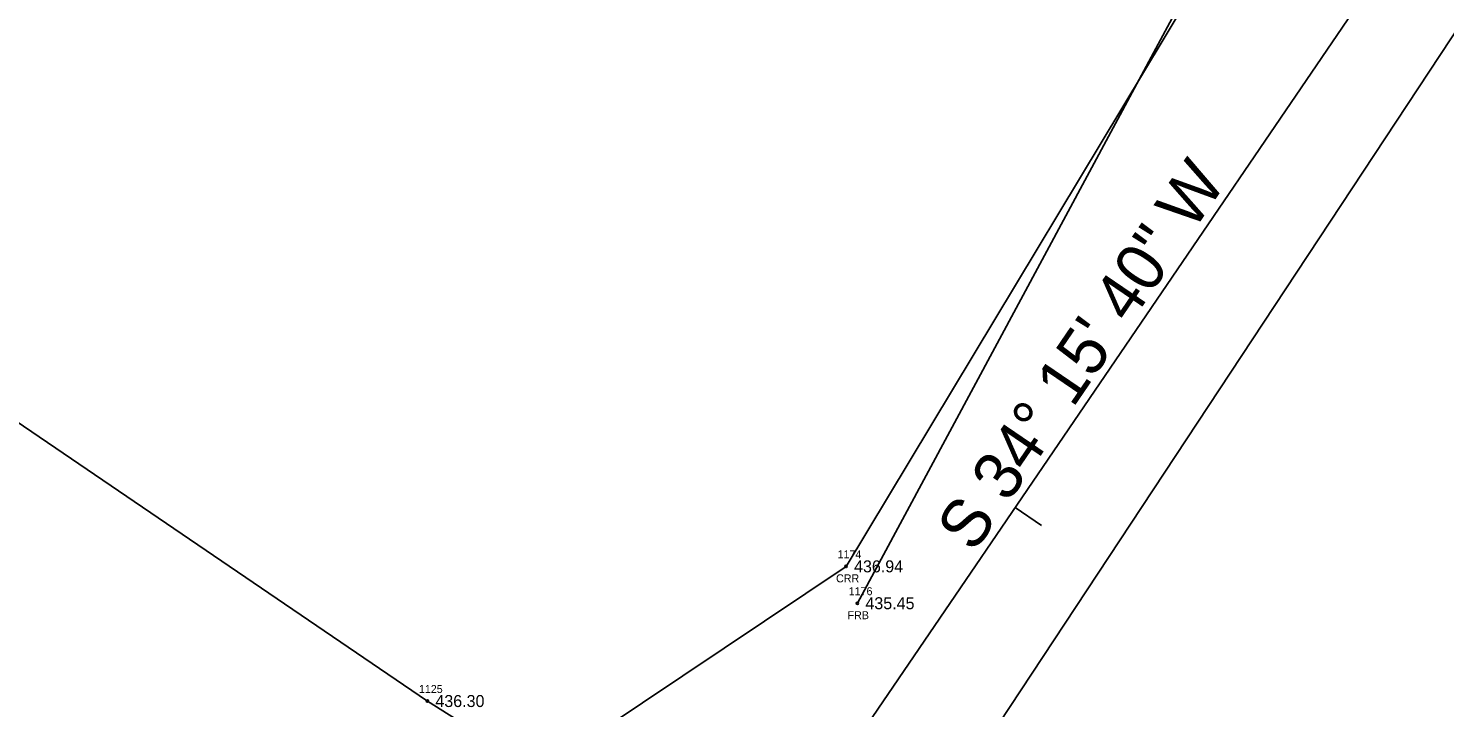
# Model space of a CAD drawing. Extents: x 1796360 to 1799195, y 895805 to 899730.
# Drawn here: x 1798350 to 1798527, y 896534.1 to 896619.1 of the extents above; entities that cross this region are included whole.
import ezdxf

# ---------------------------------------------------------------- set-up
doc = ezdxf.new("R2010")
doc.units = 0
for name, color, linetype in [('RD_EX_Fence_Other', 7, 'Continuous'), ('RD_EX_Fence_Other_txCode', 7, 'Continuous'), ('RD_EX_H2O', 7, 'Continuous'), ('RD_EX_H2O_txCode', 7, 'Continuous'), ('RD_EX_TX_Fence_Other_ELEV', 7, 'Continuous'), ('RD_EX_TX_H2O_ELEV', 7, 'Continuous'), ('RD_EX_TX_VEG_ELEV', 7, 'Continuous'), ('RD_EX_VEG', 7, 'Continuous'), ('RD_EX_VEG_txCode', 7, 'Continuous'), ('RD_HC_Cl', 7, 'Continuous'), ('RD_HC_Data', 7, 'Continuous'), ('RD_HC_Data_Tic', 7, 'Continuous'), ('RD_SMD_Locator', 7, 'Continuous')]:
    doc.layers.add(name, color=color, linetype=linetype)

msp = doc.modelspace()

# ---------------------------------------------------------------- linework, layer by layer
at = {"layer": 'RD_EX_Fence_Other'}
msp.add_lwpolyline([(1798628.94, 896919.9), (1798588.07, 896833.1), (1798545.12, 896733.55), (1798494.12, 896622.61), (1798453.58, 896547.18)], dxfattribs=at)
at = {"layer": 'RD_EX_H2O'}
for points in [[(1798663.68, 896911.94), (1798617.01, 896821.94), (1798571.81, 896720.45), (1798529.2, 896619.95), (1798471.21, 896532.04), (1798459.45, 896520.86)], [(1798502.61, 896635.66), (1798452.16, 896551.79), (1798380.86, 896504.02), (1798360.17, 896479.84), (1798335.44, 896438.68), (1798277.37, 896387.2), (1798228.36, 896339.61), (1798175.66, 896278.7), (1798083.83, 896204.11), (1798020.11, 896146.19)]]:
    msp.add_lwpolyline(points, dxfattribs=at)
at = {"layer": 'RD_EX_VEG'}
msp.add_lwpolyline([(1799022.27, 896088.33), (1798937.86, 896144.41), (1798896.41, 896211.5), (1798869.11, 896228.04), (1798778.26, 896284.04), (1798691.36, 896345.52), (1798595.8, 896403.96), (1798518.88, 896459.81), (1798399.83, 896534.95), (1798299.84, 896602.99), (1798218.96, 896659.85), (1798132.31, 896718.94), (1798044.28, 896770.93), (1797952.52, 896827.83), (1797861.07, 896893.41), (1797773.58, 896947.34)], dxfattribs=at)
at = {"layer": 'RD_HC_Cl'}
msp.add_line((1798517.64, 896624.25), (1798452.47, 896528.57), dxfattribs=at)
at = {"layer": 'RD_HC_Data_Tic'}
msp.add_line((1798473.29, 896559.13), (1798476.59, 896556.88), dxfattribs=at)
at = {"layer": 'RD_SMD_Locator'}
for centre in [(1798452.16, 896551.79), (1798453.58, 896547.18), (1798399.83, 896534.95)]:
    msp.add_circle(centre, 0.15, dxfattribs=at)

# ---------------------------------------------------------------- texts
at = {"layer": 'RD_EX_Fence_Other_txCode'}
for s, p in [('1176', (1798452.49, 896548.18)), ('FRB', (1798452.35, 896545.18))]:
    msp.add_text(s, height=1, dxfattribs=at).set_placement(p)
at = {"layer": 'RD_EX_H2O_txCode'}
for s, p in [('1174', (1798451.1, 896552.79)), ('CRR', (1798450.91, 896549.79))]:
    msp.add_text(s, height=1, dxfattribs=at).set_placement(p)
at = {"layer": 'RD_EX_TX_Fence_Other_ELEV'}
msp.add_text('435.45', height=1.5, dxfattribs=at).set_placement((1798454.58, 896546.43))
at = {"layer": 'RD_EX_TX_H2O_ELEV'}
msp.add_text('436.94', height=1.5, dxfattribs=at).set_placement((1798453.16, 896551.04))
at = {"layer": 'RD_EX_TX_VEG_ELEV'}
msp.add_text('436.30', height=1.5, dxfattribs=at).set_placement((1798400.83, 896534.2))
at = {"layer": 'RD_EX_VEG_txCode'}
msp.add_text('1125', height=1, dxfattribs=at).set_placement((1798398.77, 896535.95))
at = {"layer": 'RD_HC_Data'}
msp.add_text('S 34%%d 15\' 40" W', height=6, rotation=55.7389, dxfattribs=at).set_placement((1798468.14, 896553.35))

doc.saveas('drawing.dxf')
